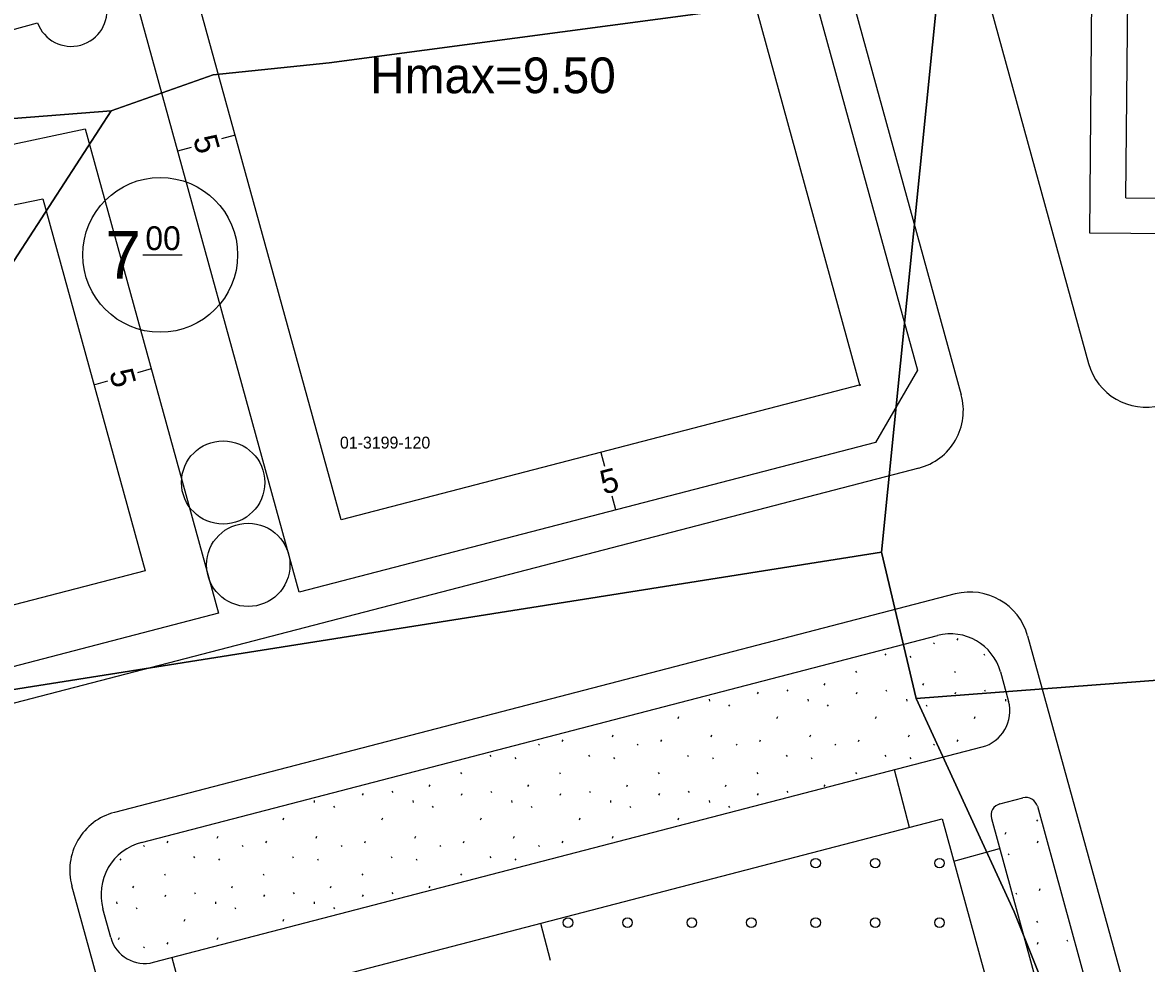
# Model space of a CAD drawing. Extents: x 419396 to 421519, y 4453567 to 4456767.
# Drawn here: x 420874.1 to 420968.5, y 4454747.5 to 4454826.5 of the extents above; entities that cross this region are included whole.
import ezdxf

# ---------------------------------------------------------------- set-up
doc = ezdxf.new("R2010")
doc.units = 0
for name, color, linetype in [('0_KADASTRO', 7, 'Continuous'), ('Level 20', 7, 'Continuous'), ('Level 28', 7, 'Continuous'), ('Level 29', 7, 'Continuous'), ('Level 30', 7, 'Continuous'), ('Level 41', 7, 'Continuous'), ('Level 43', 7, 'Continuous'), ('Level 55', 7, 'Continuous'), ('Level 58', 7, 'Continuous'), ('Level 62', 7, 'Continuous')]:
    doc.layers.add(name, color=color, linetype=linetype)

msp = doc.modelspace()

# ---------------------------------------------------------------- linework, layer by layer
at = {"layer": '0_KADASTRO'}
for points in [[(420870.03, 4454820.5), (420871.83, 4454868.52), (420908.25, 4454878.45), (420926.48, 4454883.69), (420936.04, 4454886.57), (420945.46, 4454889.45), (420954.35, 4454891.83), (420963.12, 4454894.3), (420963.18, 4454893.64), (420958.69, 4454872.71), (420958.92, 4454861.22), (420953.57, 4454833.23), (420951.07, 4454829.93), (420899.86, 4454823.11), (420890.11, 4454822.1), (420881.55, 4454819.08), (420870.47, 4454818.21)], [(420946.24, 4454782.02), (420951.07, 4454829.93), (420953.57, 4454833.23), (420961.23, 4454834.3), (421034.22, 4454835.31), (421032.89, 4454831.21), (421032.55, 4454827.39), (421031.18, 4454814.37), (421028.563, 4454776.952), (421010.39, 4454774.36), (420949.17, 4454769.71)], [(420839.81, 4454766.75), (420851.07, 4454785.89), (420859.62, 4454792.069), (420866.67, 4454800.1), (420870.74, 4454802.46), (420881.55, 4454819.08), (420890.11, 4454822.1), (420899.86, 4454823.11), (420951.07, 4454829.93), (420946.24, 4454782.02), (420872.1, 4454770.28), (420865.64, 4454769.57)], [(420743.37, 4454792.29), (420768.22, 4454796.71), (420804.28, 4454803.73), (420840.45, 4454811.21), (420870.47, 4454818.21), (420881.55, 4454819.08), (420870.74, 4454802.46), (420866.67, 4454800.1), (420859.62, 4454792.069), (420851.07, 4454785.89), (420839.81, 4454766.75), (420778.86, 4454753.97)], [(420865.64, 4454769.57), (420872.1, 4454770.28), (420946.24, 4454782.02), (420949.17, 4454769.71), (420957.38, 4454751.82), (420973.63, 4454711.21), (420973.683, 4454711.074), (420924.82, 4454692.32), (420899.17, 4454683.65), (420892.87, 4454681.75)]]:
    msp.add_lwpolyline(points, close=True, dxfattribs=at)
msp.add_lwpolyline([(420970.25, 4454598.21), (420978.09, 4454629.67), (420985.81, 4454647.83), (420992.78, 4454658.3), (420990.74, 4454672.41), (420973.683, 4454711.074), (420973.63, 4454711.21), (420957.38, 4454751.82), (420949.17, 4454769.71), (421010.39, 4454774.36), (421028.563, 4454776.952), (421116.99, 4454780.91)], dxfattribs=at)
at = {"layer": 'Level 20'}
for p, q in [((420966.759, 4454811.771), (420967.354, 4454873.787)), ((420926.436, 4454861.401), (420944.441, 4454795.977)), ((420900.864, 4454784.727), (420883.077, 4454849.357)), ((420891.97, 4454817.042), (420890.814, 4454816.724)), ((420887.15, 4454815.716), (420888.307, 4454816.034)), ((420783.702, 4454792.392), (420875.81, 4454811.695)), ((420875.81, 4454811.695), (420884.409, 4454780.451)), ((420966.759, 4454811.771), (420980.758, 4454811.637)), ((420884.93, 4454797.4), (420883.773, 4454797.081)), ((420880.109, 4454796.073), (420881.266, 4454796.391)), ((420944.492, 4454796.065), (420900.864, 4454784.727)), ((420922.678, 4454790.396), (420922.98, 4454789.235)), ((420923.935, 4454785.557), (420923.634, 4454786.718)), ((420884.409, 4454780.451), (420792.979, 4454756.692)), ((420917.605, 4454750.849), (420918.41, 4454747.752))]:
    msp.add_line(p, q, dxfattribs=at)
at = {"layer": 'Level 28'}
for p, q in [((420930.972, 4454863.757), (420949.261, 4454797.303)), ((420897.35, 4454778.648), (420878.256, 4454848.03)), ((420879.383, 4454817.551), (420890.575, 4454776.887)), ((420983.728, 4454808.607), (420963.729, 4454808.799)), ((420949.261, 4454797.303), (420945.748, 4454791.225)), ((420945.748, 4454791.225), (420897.35, 4454778.648)), ((420890.575, 4454776.887), (420798.668, 4454753.004)), ((420884.097, 4454757.639), (420950.945, 4454775.011)), ((420956.238, 4454771.952), (420956.918, 4454769.48)), ((420885.116, 4454747.572), (420954.708, 4454765.656)), ((420948.587, 4454758.9), (420947.329, 4454763.739)), ((420956.19, 4454760.875), (420958.126, 4454761.378)), ((420959.341, 4454760.676), (420972.777, 4454711.854)), ((420883.611, 4454742.015), (420951.336, 4454759.614)), ((420955.477, 4454759.642), (420968.921, 4454710.793)), ((420952.311, 4454756.07), (420956.168, 4454757.131)), ((420881.521, 4454749.652), (420880.864, 4454752.055)), ((420886.666, 4454747.975), (420887.923, 4454743.135))]:
    msp.add_line(p, q, dxfattribs=at)
for centre, radius, start, end in [((420952.04, 4454770.797), 4.354, 15.38745, 104.56688), ((420953.928, 4454768.658), 3.101, 284.56688, 15.38745), ((420958.377, 4454760.41), 1, 15.38745, 104.56688), ((420956.441, 4454759.907), 1, 104.56688, 195.38745), ((420885.238, 4454753.251), 4.534, 104.56688, 195.30085), ((420884.372, 4454750.432), 2.956, 195.30084, 284.56687)]:
    msp.add_arc(centre, radius, start, end, dxfattribs=at)
at = {"layer": 'Level 29'}
for p, q in [((420963.729, 4454808.799), (420964.38, 4454876.631)), ((420777.543, 4454796.209), (420879.383, 4454817.551)), ((420951.336, 4454759.614), (420965.329, 4454708.768))]:
    msp.add_line(p, q, dxfattribs=at)
at = {"layer": 'Level 41'}
for p, q in [((420950.619, 4454774.407), (420950.69, 4454774.301)), ((420952.607, 4454774.615), (420952.678, 4454774.775)), ((420946.534, 4454773.478), (420946.605, 4454773.371)), ((420954.827, 4454773.478), (420954.898, 4454773.371)), ((420948.633, 4454773.286), (420948.704, 4454773.179)), ((420944.078, 4454772.025), (420944.149, 4454771.918)), ((420952.371, 4454772.025), (420952.442, 4454771.918)), ((420941.437, 4454770.832), (420941.508, 4454770.991)), ((420949.73, 4454770.832), (420949.801, 4454770.991)), ((420931.773, 4454769.657), (420931.791, 4454769.497)), ((420935.843, 4454770.103), (420935.915, 4454770.263)), ((420938.308, 4454770.448), (420938.379, 4454770.341)), ((420940.066, 4454769.657), (420940.084, 4454769.497)), ((420944.136, 4454770.103), (420944.208, 4454770.263)), ((420946.601, 4454770.448), (420946.672, 4454770.341)), ((420948.359, 4454769.657), (420948.377, 4454769.497)), ((420952.429, 4454770.103), (420952.501, 4454770.263)), ((420954.894, 4454770.448), (420954.965, 4454770.341)), ((420956.652, 4454769.657), (420956.67, 4454769.497)), ((420933.403, 4454769.187), (420933.473, 4454769.08)), ((420941.696, 4454769.187), (420941.766, 4454769.08)), ((420949.989, 4454769.187), (420950.059, 4454769.08)), ((420929.166, 4454768.043), (420929.238, 4454768.203)), ((420937.459, 4454768.043), (420937.531, 4454768.203)), ((420945.752, 4454768.043), (420945.824, 4454768.203)), ((420954.045, 4454768.043), (420954.117, 4454768.203)), ((420917.447, 4454765.897), (420917.518, 4454765.791)), ((420919.435, 4454766.105), (420919.506, 4454766.265)), ((420923.645, 4454766.513), (420923.715, 4454766.673)), ((420925.74, 4454765.897), (420925.811, 4454765.791)), ((420927.728, 4454766.105), (420927.799, 4454766.265)), ((420931.938, 4454766.513), (420932.008, 4454766.673)), ((420934.033, 4454765.897), (420934.104, 4454765.791)), ((420936.021, 4454766.105), (420936.092, 4454766.265)), ((420940.231, 4454766.513), (420940.301, 4454766.673)), ((420942.326, 4454765.897), (420942.397, 4454765.791)), ((420944.314, 4454766.105), (420944.385, 4454766.265)), ((420948.524, 4454766.513), (420948.594, 4454766.673)), ((420950.619, 4454765.897), (420950.69, 4454765.791)), ((420952.607, 4454766.105), (420952.678, 4454766.265)), ((420913.362, 4454764.968), (420913.433, 4454764.861)), ((420921.655, 4454764.968), (420921.726, 4454764.861)), ((420929.948, 4454764.968), (420930.019, 4454764.861)), ((420938.241, 4454764.968), (420938.312, 4454764.861)), ((420946.534, 4454764.968), (420946.605, 4454764.861)), ((420915.461, 4454764.776), (420915.532, 4454764.669)), ((420923.754, 4454764.776), (420923.825, 4454764.669)), ((420932.047, 4454764.776), (420932.118, 4454764.669)), ((420940.34, 4454764.776), (420940.411, 4454764.669)), ((420948.633, 4454764.776), (420948.704, 4454764.669)), ((420910.906, 4454763.515), (420910.977, 4454763.408)), ((420919.199, 4454763.515), (420919.27, 4454763.408)), ((420927.492, 4454763.515), (420927.563, 4454763.408)), ((420935.785, 4454763.515), (420935.856, 4454763.408)), ((420944.078, 4454763.515), (420944.149, 4454763.408)), ((420908.265, 4454762.322), (420908.336, 4454762.481)), ((420916.558, 4454762.322), (420916.629, 4454762.481)), ((420924.851, 4454762.322), (420924.922, 4454762.481)), ((420933.144, 4454762.322), (420933.215, 4454762.481)), ((420941.437, 4454762.322), (420941.508, 4454762.481)), ((420898.601, 4454761.147), (420898.619, 4454760.987)), ((420902.671, 4454761.593), (420902.743, 4454761.753)), ((420905.136, 4454761.938), (420905.207, 4454761.831)), ((420906.894, 4454761.147), (420906.912, 4454760.987)), ((420910.964, 4454761.593), (420911.036, 4454761.753)), ((420913.429, 4454761.938), (420913.5, 4454761.831)), ((420915.187, 4454761.147), (420915.205, 4454760.987)), ((420919.257, 4454761.593), (420919.329, 4454761.753)), ((420921.722, 4454761.938), (420921.793, 4454761.831)), ((420923.48, 4454761.147), (420923.498, 4454760.987)), ((420927.55, 4454761.593), (420927.622, 4454761.753)), ((420930.015, 4454761.938), (420930.086, 4454761.831)), ((420931.773, 4454761.147), (420931.791, 4454760.987)), ((420935.843, 4454761.593), (420935.915, 4454761.753)), ((420938.308, 4454761.938), (420938.379, 4454761.831)), ((420900.231, 4454760.677), (420900.301, 4454760.57)), ((420908.524, 4454760.677), (420908.594, 4454760.57)), ((420916.817, 4454760.677), (420916.887, 4454760.57)), ((420925.11, 4454760.677), (420925.18, 4454760.57)), ((420933.403, 4454760.677), (420933.473, 4454760.57)), ((420895.994, 4454759.533), (420896.066, 4454759.693)), ((420904.287, 4454759.533), (420904.359, 4454759.693)), ((420912.58, 4454759.533), (420912.652, 4454759.693)), ((420920.873, 4454759.533), (420920.945, 4454759.693)), ((420929.166, 4454759.533), (420929.238, 4454759.693)), ((420959.276, 4454759.53), (420959.347, 4454759.423)), ((420956.635, 4454758.337), (420956.706, 4454758.496)), ((420884.275, 4454757.387), (420884.346, 4454757.281)), ((420886.263, 4454757.595), (420886.334, 4454757.755)), ((420890.473, 4454758.003), (420890.543, 4454758.163)), ((420892.568, 4454757.387), (420892.639, 4454757.281)), ((420894.556, 4454757.595), (420894.627, 4454757.755)), ((420898.766, 4454758.003), (420898.836, 4454758.163)), ((420900.861, 4454757.387), (420900.932, 4454757.281)), ((420902.849, 4454757.595), (420902.92, 4454757.755)), ((420907.059, 4454758.003), (420907.129, 4454758.163)), ((420909.154, 4454757.387), (420909.225, 4454757.281)), ((420911.142, 4454757.595), (420911.213, 4454757.755)), ((420915.352, 4454758.003), (420915.422, 4454758.163)), ((420917.447, 4454757.387), (420917.518, 4454757.281)), ((420919.435, 4454757.595), (420919.506, 4454757.755)), ((420923.645, 4454758.003), (420923.715, 4454758.163)), ((420959.334, 4454757.608), (420959.406, 4454757.768)), ((420888.483, 4454756.458), (420888.554, 4454756.351)), ((420896.776, 4454756.458), (420896.847, 4454756.351)), ((420905.069, 4454756.458), (420905.14, 4454756.351)), ((420913.362, 4454756.458), (420913.433, 4454756.351)), ((420956.894, 4454756.692), (420956.964, 4454756.585)), ((420882.289, 4454756.266), (420882.36, 4454756.159)), ((420890.582, 4454756.266), (420890.653, 4454756.159)), ((420898.875, 4454756.266), (420898.946, 4454756.159)), ((420907.168, 4454756.266), (420907.239, 4454756.159)), ((420915.461, 4454756.266), (420915.532, 4454756.159)), ((420886.027, 4454755.005), (420886.098, 4454754.898)), ((420894.32, 4454755.005), (420894.391, 4454754.898)), ((420902.613, 4454755.005), (420902.684, 4454754.898)), ((420910.906, 4454755.005), (420910.977, 4454754.898)), ((420883.386, 4454753.812), (420883.457, 4454753.971)), ((420891.679, 4454753.812), (420891.75, 4454753.971)), ((420899.972, 4454753.812), (420900.043, 4454753.971)), ((420908.265, 4454753.812), (420908.336, 4454753.971)), ((420959.512, 4454753.61), (420959.583, 4454753.77)), ((420886.085, 4454753.083), (420886.157, 4454753.243)), ((420888.55, 4454753.428), (420888.621, 4454753.321)), ((420894.378, 4454753.083), (420894.45, 4454753.243)), ((420896.843, 4454753.428), (420896.914, 4454753.321)), ((420902.671, 4454753.083), (420902.743, 4454753.243)), ((420905.136, 4454753.428), (420905.207, 4454753.321)), ((420957.524, 4454753.402), (420957.595, 4454753.296)), ((420882.015, 4454752.637), (420882.033, 4454752.477)), ((420883.645, 4454752.167), (420883.715, 4454752.06)), ((420890.308, 4454752.637), (420890.326, 4454752.477)), ((420891.938, 4454752.167), (420892.008, 4454752.06)), ((420898.601, 4454752.637), (420898.619, 4454752.477)), ((420900.231, 4454752.167), (420900.301, 4454752.06)), ((420887.701, 4454751.023), (420887.773, 4454751.183)), ((420895.994, 4454751.023), (420896.066, 4454751.183)), ((420959.276, 4454751.02), (420959.347, 4454750.913)), ((420882.18, 4454749.493), (420882.25, 4454749.653)), ((420884.275, 4454748.877), (420884.346, 4454748.771)), ((420886.263, 4454749.085), (420886.334, 4454749.245)), ((420890.473, 4454749.493), (420890.543, 4454749.653)), ((420959.334, 4454749.098), (420959.406, 4454749.258)), ((420961.799, 4454749.443), (420961.87, 4454749.336))]:
    msp.add_line(p, q, dxfattribs=at)
at = {"layer": 'Level 43'}
for centre in [(420940.719, 4454755.9), (420945.719, 4454755.9), (420951.119, 4454755.9), (420919.919, 4454750.9), (420924.919, 4454750.9), (420930.319, 4454750.9), (420935.319, 4454750.9), (420940.719, 4454750.9), (420945.719, 4454750.9), (420951.119, 4454750.9)]:
    msp.add_circle(centre, 0.4, dxfattribs=at)
at = {"layer": 'Level 55'}
for centre in [(420890.962, 4454787.863), (420893.067, 4454780.947)]:
    msp.add_circle(centre, 3.5, dxfattribs=at)
at = {"layer": 'Level 58'}
msp.add_line((420884.231, 4454806.98), (420887.528, 4454806.98), dxfattribs=at)
msp.add_circle((420885.68, 4454806.98), 6.5, dxfattribs=at)
at = {"layer": 'Level 62'}
for p, q in [((420923.607, 4454943.285), (420963.627, 4454797.866)), ((420933.616, 4454865.46), (420952.942, 4454795.238)), ((420870.554, 4454825.14), (420875.372, 4454826.477)), ((420949.379, 4454789.072), (420799.485, 4454750.12)), ((420952.436, 4454778.501), (420881.826, 4454760.152)), ((420958.515, 4454774.988), (420989.766, 4454661.433)), ((420914.048, 4454623.186), (420878.261, 4454753.993))]:
    msp.add_line(p, q, dxfattribs=at)
for centre, radius, start, end in [((420878.202, 4454827.499), 3.009, 199.85243, 11.16689), ((420968.448, 4454799.193), 5, 195.38745, 284.56688), ((420948.121, 4454793.911), 5, 284.56688, 15.38745), ((420953.694, 4454773.662), 5, 15.38745, 104.56688), ((420883.084, 4454755.313), 5, 104.56688, 195.30085)]:
    msp.add_arc(centre, radius, start, end, dxfattribs=at)

# ---------------------------------------------------------------- texts
at = {"layer": '0_KADASTRO'}
msp.add_text('01-3199-120', height=1, dxfattribs=at).set_placement((420900.77, 4454790.714))
at = {"layer": 'Level 20'}
for rotation, p in [(285.38746, (420888.419, 4454816.756)), (285.38746, (420881.379, 4454797.114)), (14.56686, (420922.913, 4454786.841))]:
    msp.add_text('5', height=2, rotation=rotation, dxfattribs=at).set_placement(p)
at = {"layer": 'Level 30'}
msp.add_text('Hmax=9.50', height=3, dxfattribs=at).set_placement((420903.308, 4454820.556))
at = {"layer": 'Level 58'}
for s, height, p in [('00', 1.9983, (420884.431, 4454807.38)), ('7', 3.997, (420881.083, 4454804.982))]:
    msp.add_text(s, height=height, dxfattribs=at).set_placement(p)

doc.saveas('drawing.dxf')
